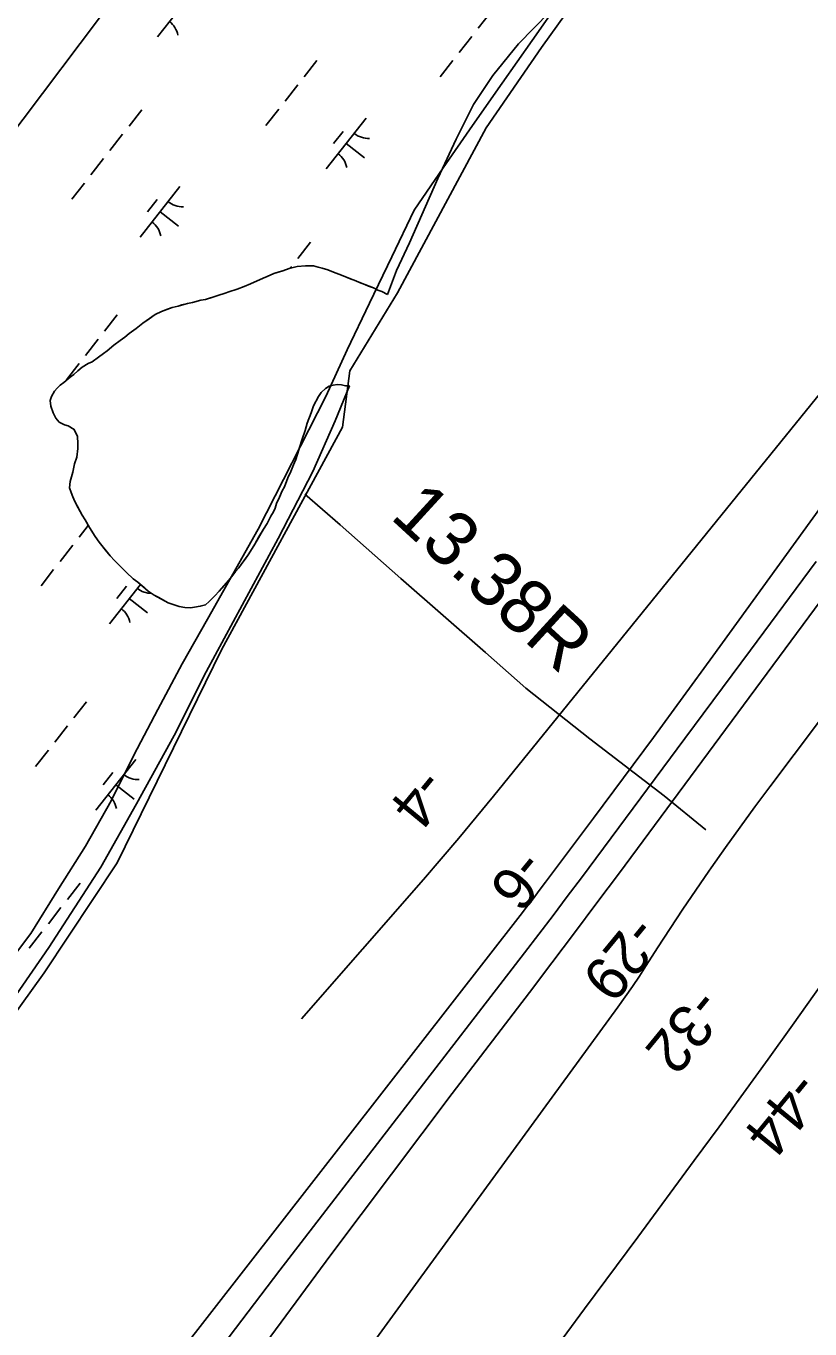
# Model space of a CAD drawing. Extents: x 3896831 to 3918110, y 171006 to 193349.
# Drawn here: x 3908456 to 3909064, y 182533 to 183545 of the extents above; entities that cross this region are included whole.
import ezdxf

# ---------------------------------------------------------------- set-up
doc = ezdxf.new("R2010")
doc.units = 0
for name, color, linetype in [('V-LEVE-TOET', 7, 'Continuous'), ('V-RIVR-EDGE', 7, 'Continuous'), ('V-RIVR-RANG', 7, 'Continuous'), ('V-RRAP-FSHR', 7, 'Continuous'), ('V-STRM-FMON', 7, 'Continuous'), ('V-TOPO-DPTH', 7, 'Continuous'), ('V-TOPO-MINR', 7, 'Continuous'), ('V-TOPO-SHOR', 7, 'Continuous'), ('V-UTIL-LINE', 7, 'Continuous'), ('V-WETL-SWMP', 7, 'Continuous')]:
    doc.layers.add(name, color=color, linetype=linetype)

msp = doc.modelspace()

# ---------------------------------------------------------------- linework, layer by layer
at = {"layer": 'V-LEVE-TOET'}
msp.add_lwpolyline([(3908983.2, 182920.7), (3908950.9, 182947.2), (3908893.3, 182991.3), (3908843.5, 183030.7), (3908812.3, 183058.4), (3908746.6, 183115.8), (3908699.5, 183157.6), (3908672.2, 183181.3)], dxfattribs=at)
at = {"layer": 'V-RIVR-EDGE'}
msp.add_lwpolyline([(3908938.3, 183643.2), (3908855.6, 183528), (3908812.8, 183465.7), (3908744, 183337.5), (3908706.9, 183277.1), (3908701.3, 183233.4), (3908607.5, 183060.6), (3908526.6, 182895.2), (3908469.9, 182809.7), (3908343.6, 182634.1), (3908310.1, 182599.7), (3908286.9, 182575.5), (3908257.1, 182538.4), (3908237.6, 182494.7), (3908204.2, 182458.4), (3908146.6, 182377.6), (3908019.3, 182222.4), (3907957, 182142.5), (3907934.7, 182118.4), (3907892, 182064.5), (3907843.6, 182017.1), (3907794.4, 181978)], dxfattribs=at)
at = {"layer": 'V-RRAP-FSHR'}
msp.add_lwpolyline([(3908870.9, 183565.8), (3908848.5, 183533.3), (3908825.1, 183500.2), (3908802.2, 183467.4), (3908779.3, 183434.6), (3908756.8, 183401.6), (3908739.5, 183365.6), (3908722.2, 183329.5), (3908704.9, 183293.4), (3908688.4, 183257), (3908635.8, 183154), (3908616.2, 183119.1), (3908596.5, 183084.3), (3908576.9, 183049.5), (3908558, 183014.2), (3908539.5, 182978.7), (3908521.9, 182943.2), (3908501.9, 182908.1), (3908480.9, 182874.9), (3908459.4, 182840.4), (3908435.9, 182808.9)], dxfattribs=at)
at = {"layer": 'V-TOPO-DPTH'}
for points in [[(3908466.3, 182375.2), (3908839.2, 182854.4), (3908844.1, 182860.8), (3908849.1, 182867.2), (3908854, 182873.7), (3908858.9, 182880.2), (3908895.9, 182929.7), (3908919.2, 182961.1), (3908942.5, 182992.5), (3908965.5, 183024), (3908988.5, 183055.6), (3909269, 183442.6)], [(3909374.9, 183409), (3909032.9, 182954.2), (3909021.3, 182938.6), (3909009.8, 182922.9), (3908998.5, 182907.1), (3908987.3, 182891.2), (3908985.5, 182888.7), (3908975.4, 182873.9), (3908965.4, 182859.1), (3908955.5, 182844.2), (3908945.8, 182829.2), (3908937, 182815.5), (3908931.6, 182807.3), (3908926.2, 182799.2), (3908920.6, 182791.2), (3908914.9, 182783.2), (3908760.1, 182570.7), (3908712, 182504.6)], [(3908712, 182504.6), (3908760.1, 182570.7), (3908914.9, 182783.2), (3908920.6, 182791.2), (3908926.2, 182799.2), (3908931.6, 182807.3), (3908937, 182815.5), (3908945.8, 182829.2), (3908955.5, 182844.2), (3908965.4, 182859.1), (3908975.4, 182873.9), (3908985.5, 182888.7), (3908987.3, 182891.2), (3908998.5, 182907.1), (3909009.8, 182922.9), (3909021.3, 182938.6), (3909032.9, 182954.2), (3909374.9, 183409)], [(3909122.5, 183166.5), (3908916.1, 182887.4), (3908898.7, 182864), (3908881.3, 182840.8), (3908863.8, 182817.6), (3908846.3, 182794.4), (3908786.5, 182716), (3908739.2, 182653.5), (3908692.3, 182590.8), (3908645.7, 182527.7), (3908599.5, 182464.5), (3908429.5, 182230.1), (3908422, 182219.8), (3908414.6, 182209.4), (3908407.3, 182199), (3908400, 182188.5), (3908378.2, 182157.1)], [(3908378.2, 182157.1), (3908400, 182188.5), (3908407.3, 182199), (3908414.6, 182209.4), (3908422, 182219.8), (3908429.5, 182230.1), (3908599.5, 182464.5), (3908645.7, 182527.7), (3908692.3, 182590.8), (3908739.2, 182653.5), (3908786.5, 182716), (3908846.3, 182794.4), (3908863.8, 182817.6), (3908881.3, 182840.8), (3908898.7, 182864), (3908916.1, 182887.4), (3909122.5, 183166.5)], [(3909253.5, 183055.4), (3909050.4, 182769.2), (3909031.5, 182742.8), (3909012.5, 182716.4), (3908993.4, 182690.2), (3908974.1, 182664), (3908930.3, 182604.7), (3908889.1, 182549), (3908847.9, 182493.2), (3908806.8, 182437.4), (3908765.7, 182381.6), (3908589.7, 182142.7), (3908578.7, 182127.6), (3908567.7, 182112.5), (3908556.7, 182097.4), (3908545.8, 182082.3), (3908506.8, 182027.9), (3908476.5, 181985.6), (3908446.1, 181943.2), (3908415.8, 181900.9), (3908385.4, 181858.5), (3908232.7, 181644.9)], [(3909253.5, 183055.4), (3909050.4, 182769.2), (3909031.5, 182742.8), (3909012.5, 182716.4), (3908993.4, 182690.2), (3908974.1, 182664), (3908930.3, 182604.7), (3908889.1, 182549), (3908847.9, 182493.2), (3908806.8, 182437.4), (3908765.7, 182381.6), (3908589.7, 182142.7), (3908578.7, 182127.6), (3908567.7, 182112.5), (3908556.7, 182097.4), (3908545.8, 182082.3), (3908506.8, 182027.9), (3908476.5, 181985.6), (3908446.1, 181943.2), (3908415.8, 181900.9), (3908385.4, 181858.5), (3908232.7, 181644.9)]]:
    msp.add_lwpolyline(points, dxfattribs=at)
at = {"layer": 'V-TOPO-MINR'}
for points in [[(3909295.6, 183556.8), (3909277.2, 183528.3), (3909258.1, 183500.2), (3909238.7, 183472.4), (3909218.8, 183444.9), (3909198.5, 183417.7), (3909177.8, 183390.8), (3909156.6, 183364.3), (3908818.5, 182946.9), (3908805.1, 182930.6), (3908791.6, 182914.4), (3908777.9, 182898.3), (3908764.1, 182882.3), (3908669.4, 182774)], [(3909269, 183442.6), (3908988.5, 183055.6), (3908965.5, 183024), (3908942.5, 182992.5), (3908919.2, 182961.1), (3908895.9, 182929.7), (3908858.9, 182880.2), (3908854, 182873.7), (3908849.1, 182867.2), (3908844.1, 182860.8), (3908839.2, 182854.4), (3908466.3, 182375.2)], [(3909374.9, 183409), (3909032.9, 182954.2), (3909021.3, 182938.6), (3909009.8, 182922.9), (3908998.5, 182907.1), (3908987.3, 182891.2), (3908985.5, 182888.7), (3908975.4, 182873.9), (3908965.4, 182859.1), (3908955.5, 182844.2), (3908945.8, 182829.2), (3908937, 182815.5), (3908931.6, 182807.3), (3908926.2, 182799.2), (3908920.6, 182791.2), (3908914.9, 182783.2), (3908760.1, 182570.7), (3908712, 182504.6)], [(3909122.5, 183166.5), (3908916.1, 182887.4), (3908898.7, 182864), (3908881.3, 182840.8), (3908863.8, 182817.6), (3908846.3, 182794.4), (3908786.5, 182716), (3908739.2, 182653.5), (3908692.3, 182590.8), (3908645.7, 182527.7), (3908599.5, 182464.5), (3908429.5, 182230.1), (3908422, 182219.8), (3908414.6, 182209.4), (3908407.3, 182199), (3908400, 182188.5), (3908378.2, 182157.1)], [(3909068.7, 183129), (3909017.8, 183060.3), (3908966.9, 182991.6), (3908886.6, 182883.6), (3908875.7, 182869), (3908864.7, 182854.4), (3908853.6, 182839.9), (3908842.5, 182825.4), (3908652.8, 182579), (3908608.4, 182520.9), (3908564.4, 182462.6), (3908520.8, 182403.8), (3908477.5, 182344.9), (3908418.3, 182263.6), (3908404.8, 182245.1), (3908391.3, 182226.7), (3908377.7, 182208.4), (3908364, 182190), (3908359.4, 182183.7), (3907444.9, 181069.3)], [(3909253.5, 183055.4), (3909050.4, 182769.2), (3909031.5, 182742.8), (3909012.5, 182716.4), (3908993.4, 182690.2), (3908974.1, 182664), (3908930.3, 182604.7), (3908889.1, 182549), (3908847.9, 182493.2), (3908806.8, 182437.4), (3908765.7, 182381.6), (3908589.7, 182142.7), (3908578.7, 182127.6), (3908567.7, 182112.5), (3908556.7, 182097.4), (3908545.8, 182082.3), (3908506.8, 182027.9), (3908476.5, 181985.6), (3908446.1, 181943.2), (3908415.8, 181900.9), (3908385.4, 181858.5), (3908232.7, 181644.9)]]:
    msp.add_lwpolyline(points, dxfattribs=at)
at = {"layer": 'V-TOPO-SHOR'}
for points in [[(3908518.7, 183292.6), (3908523.9, 183297), (3908528.8, 183300.5), (3908532.3, 183303.1), (3908535.7, 183306.1), (3908541.2, 183309.9), (3908546.4, 183314), (3908551.3, 183317.5), (3908555.9, 183320.7), (3908560.8, 183323.1), (3908564.8, 183324.6), (3908569.2, 183326.1), (3908573.8, 183327.3), (3908576.7, 183328.2), (3908581, 183329.4), (3908584.8, 183330), (3908591.4, 183331.8), (3908594.9, 183332.4), (3908600.7, 183334.2), (3908604.7, 183335.4), (3908610.2, 183337.2), (3908613.1, 183338.3), (3908619.5, 183340.4), (3908625, 183342.5), (3908629.9, 183344.6), (3908634.5, 183346.7), (3908639.7, 183349), (3908642.9, 183350.2), (3908648.1, 183352.6), (3908652.1, 183353.8), (3908655, 183354.7), (3908659.9, 183356.4), (3908666, 183357.9), (3908672.7, 183358.6), (3908678.8, 183358.4), (3908682.5, 183357.5), (3908685.4, 183356.7), (3908689.8, 183355.3), (3908694.2, 183353.6), (3908698.5, 183352.1), (3908703.2, 183350.2), (3908706.7, 183348.7), (3908711.6, 183346.8), (3908714.5, 183345.6), (3908718.6, 183343.9), (3908721.5, 183342.8), (3908725.3, 183341.4), (3908728.8, 183339.7), (3908731.7, 183338.5), (3908736.1, 183336.3)], [(3908706.8, 183265.5), (3908703.6, 183265.5), (3908700.4, 183266.1), (3908697.3, 183266.3), (3908694.1, 183266), (3908690.9, 183265.1), (3908688, 183263.3), (3908684.8, 183260.1), (3908682.6, 183257.2), (3908678.8, 183249.9), (3908676.9, 183244.4), (3908674, 183236.3), (3908672.3, 183230.7), (3908670.1, 183224.1), (3908667.8, 183216.8), (3908666.1, 183211.6), (3908665, 183208.1), (3908663.3, 183204), (3908661.3, 183198.8), (3908659, 183194.1), (3908656.2, 183187.1), (3908654.5, 183183.9), (3908652.5, 183179), (3908650.2, 183174), (3908649.1, 183170.5), (3908647.7, 183167.6), (3908645.7, 183164.1), (3908642.8, 183158.6), (3908640, 183154.2), (3908636.5, 183148.1), (3908633.4, 183142.6), (3908631.1, 183139.1), (3908628, 183134.1), (3908625.7, 183130.9), (3908622.8, 183126.8), (3908620.8, 183124.2), (3908618.2, 183121.3), (3908615.4, 183117.5), (3908612.8, 183114.3), (3908607.9, 183108.7), (3908605.6, 183106.1), (3908602.2, 183102.3), (3908597.9, 183097.9), (3908595, 183095.3), (3908590.9, 183094.3), (3908586.6, 183093.7), (3908583.4, 183093.1), (3908579.1, 183093.4), (3908574.7, 183094.2), (3908569.8, 183095.6), (3908566, 183097), (3908558.7, 183101), (3908555.2, 183103), (3908550.5, 183105.9), (3908547.3, 183108.8), (3908542.4, 183113.1), (3908538.8, 183115.6), (3908533.6, 183120.5), (3908528.3, 183126), (3908524.5, 183129.7), (3908521, 183133.4), (3908517.5, 183137.8), (3908512.5, 183144.1), (3908509.3, 183148.4), (3908504.9, 183155.3), (3908501.6, 183161.4), (3908499.3, 183165.1), (3908496.3, 183170.6), (3908493.7, 183175.5), (3908492.2, 183179.3), (3908490.7, 183182.5), (3908489.5, 183186.2), (3908490.1, 183191.2), (3908492, 183198.4), (3908493.4, 183204.8), (3908495.1, 183210), (3908495.9, 183216.7), (3908495.9, 183220.5), (3908495.6, 183226), (3908493.2, 183231.5), (3908488.5, 183234.3), (3908485.6, 183235.2), (3908481.5, 183237.2), (3908478.9, 183240.3), (3908476.8, 183244.4), (3908475.1, 183249.6), (3908474.4, 183253.9), (3908475.6, 183257.1), (3908477.8, 183261.2), (3908479.9, 183263.5), (3908482.2, 183265.9), (3908485, 183267.9), (3908489.9, 183272), (3908492.8, 183274.1), (3908496, 183277), (3908499.4, 183279.9), (3908504, 183282.6), (3908507.2, 183284.1), (3908512.1, 183287.6), (3908515.9, 183290.5), (3908518.7, 183292.6)]]:
    msp.add_lwpolyline(points, dxfattribs=at)
at = {"layer": 'V-UTIL-LINE'}
msp.add_lwpolyline([(3902278.5, 176090.1), (3904647.1, 178894.7), (3905719.5, 180143.9), (3906520.8, 181098.4), (3907322.1, 182041.1), (3907534.2, 182300.3), (3908041, 182924.9), (3909514, 184881.1), (3910138.5, 185694.2), (3909821.8, 185935.5), (3909829.3, 185945.1), (3909882.7, 185907)], dxfattribs=at)
at = {"layer": 'V-WETL-SWMP'}
for p, q in [((3908588.7, 183575.7), (3908557.8, 183536.3)), ((3908816.4, 183555.5), (3908806.6, 183542.9)), ((3908837.9, 183530.9), (3908861.8, 183555.3)), ((3908801.6, 183536.6), (3908791.8, 183524)), ((3908817.8, 183506.2), (3908837.9, 183530.9)), ((3908681.4, 183517.9), (3908671.5, 183505.3)), ((3908786.8, 183517.8), (3908777, 183505.2)), ((3908802.8, 183483.7), (3908817.8, 183506.2)), ((3908666.6, 183499), (3908656.7, 183486.4)), ((3908545.5, 183479.5), (3908535.7, 183466.9)), ((3908651.8, 183480.1), (3908641.9, 183467.5)), ((3908789.5, 183456.9), (3908802.8, 183483.7)), ((3908719.6, 183473.1), (3908688.7, 183433.7)), ((3908530.7, 183460.6), (3908520.8, 183448)), ((3908701.8, 183462.9), (3908694.4, 183453.4)), ((3908704.2, 183453.4), (3908718.3, 183442.3)), ((3908775.2, 183426.2), (3908789.5, 183456.9)), ((3908515.9, 183441.7), (3908506, 183429.1)), ((3908501.1, 183422.8), (3908491.2, 183410.3)), ((3908575.2, 183420.1), (3908544.4, 183380.8)), ((3908753.2, 183376.3), (3908775.2, 183426.2)), ((3908557.4, 183409.9), (3908550, 183400.5)), ((3908559.8, 183400.4), (3908574, 183389.3)), ((3908676.4, 183376.9), (3908666.6, 183364.3)), ((3908743.1, 183354.9), (3908753.2, 183376.3)), ((3908659.9, 183356.4), (3908666, 183357.9)), ((3908661.6, 183358), (3908660.5, 183356.6)), ((3908666, 183357.9), (3908672.7, 183358.6)), ((3908672.7, 183358.6), (3908678.8, 183358.4)), ((3908678.8, 183358.4), (3908682.5, 183357.5)), ((3908629.9, 183344.6), (3908639.7, 183349)), ((3908639.7, 183349), (3908642.9, 183350.2)), ((3908642.9, 183350.2), (3908648.1, 183352.6)), ((3908648.1, 183352.6), (3908655, 183354.7)), ((3908655, 183354.7), (3908659.9, 183356.4)), ((3908682.5, 183357.5), (3908685.4, 183356.7)), ((3908685.4, 183356.7), (3908689.8, 183355.3)), ((3908689.8, 183355.3), (3908694.2, 183353.6)), ((3908694.2, 183353.6), (3908698.5, 183352.1)), ((3908698.5, 183352.1), (3908703.2, 183350.2)), ((3908703.2, 183350.2), (3908718.6, 183343.9)), ((3908736.1, 183336.3), (3908743.1, 183354.9)), ((3908610.2, 183337.2), (3908613.1, 183338.3)), ((3908613.1, 183338.3), (3908619.5, 183340.4)), ((3908619.5, 183340.4), (3908625, 183342.5)), ((3908625, 183342.5), (3908629.9, 183344.6)), ((3908718.6, 183343.9), (3908725.3, 183341.4)), ((3908725.3, 183341.4), (3908728.8, 183339.7)), ((3908728.8, 183339.7), (3908731.7, 183338.5)), ((3908731.7, 183338.5), (3908736.1, 183336.3)), ((3908573.8, 183327.3), (3908581, 183329.4)), ((3908581, 183329.4), (3908584.8, 183330)), ((3908584.8, 183330), (3908591.4, 183331.8)), ((3908591.4, 183331.8), (3908594.9, 183332.4)), ((3908594.9, 183332.4), (3908604.7, 183335.4)), ((3908604.7, 183335.4), (3908610.2, 183337.2)), ((3908526.6, 183320.4), (3908516.7, 183307.8)), ((3908546.4, 183314), (3908555.9, 183320.7)), ((3908555.9, 183320.7), (3908560.8, 183323.1)), ((3908560.8, 183323.1), (3908569.2, 183326.1)), ((3908569.2, 183326.1), (3908573.8, 183327.3)), ((3908535.7, 183306.1), (3908541.2, 183309.9)), ((3908541.2, 183309.9), (3908546.4, 183314)), ((3908511.8, 183301.5), (3908501.9, 183288.9)), ((3908523.9, 183297), (3908528.8, 183300.5)), ((3908528.8, 183300.5), (3908532.3, 183303.1)), ((3908532.3, 183303.1), (3908535.7, 183306.1)), ((3908507.2, 183284.1), (3908512.1, 183287.6)), ((3908512.1, 183287.6), (3908515.9, 183290.5)), ((3908515.9, 183290.5), (3908518.7, 183292.6)), ((3908518.7, 183292.6), (3908523.9, 183297)), ((3908497, 183282.6), (3908487.1, 183270)), ((3908492.8, 183274.1), (3908496, 183277)), ((3908496, 183277), (3908499.4, 183279.9)), ((3908499.4, 183279.9), (3908504, 183282.6)), ((3908504, 183282.6), (3908507.2, 183284.1)), ((3908482.2, 183265.9), (3908485, 183267.9)), ((3908485, 183267.9), (3908489.9, 183272)), ((3908489.9, 183272), (3908492.8, 183274.1)), ((3908474.4, 183253.9), (3908475.6, 183257.1)), ((3908475.6, 183257.1), (3908477.8, 183261.2)), ((3908477.8, 183261.2), (3908479.9, 183263.5)), ((3908479.9, 183263.5), (3908482.2, 183265.9)), ((3908682.6, 183257.2), (3908678.8, 183249.9)), ((3908684.8, 183260.1), (3908682.6, 183257.2)), ((3908688, 183263.3), (3908684.8, 183260.1)), ((3908690.9, 183265.1), (3908688, 183263.3)), ((3908694.1, 183266), (3908690.9, 183265.1)), ((3908697.3, 183266.3), (3908694.1, 183266)), ((3908695.5, 183238.2), (3908706.8, 183265.5)), ((3908700.4, 183266.1), (3908697.3, 183266.3)), ((3908703.6, 183265.5), (3908700.4, 183266.1)), ((3908706.8, 183265.5), (3908703.6, 183265.5)), ((3908475.1, 183249.6), (3908474.4, 183253.9)), ((3908476.8, 183244.4), (3908475.1, 183249.6)), ((3908678.8, 183249.9), (3908676.9, 183244.4)), ((3908478.9, 183240.3), (3908476.8, 183244.4)), ((3908481.5, 183237.2), (3908478.9, 183240.3)), ((3908485.6, 183235.2), (3908481.5, 183237.2)), ((3908676.9, 183244.4), (3908674, 183236.3)), ((3908678.4, 183199), (3908695.5, 183238.2)), ((3908488.5, 183234.3), (3908485.6, 183235.2)), ((3908493.2, 183231.5), (3908488.5, 183234.3)), ((3908495.6, 183226), (3908493.2, 183231.5)), ((3908672.3, 183230.7), (3908670.1, 183224.1)), ((3908674, 183236.3), (3908672.3, 183230.7)), ((3908495.1, 183210), (3908495.9, 183216.7)), ((3908495.9, 183220.5), (3908495.6, 183226)), ((3908495.9, 183216.7), (3908495.9, 183220.5)), ((3908670.1, 183224.1), (3908665, 183208.1)), ((3908493.4, 183204.8), (3908495.1, 183210)), ((3908665, 183208.1), (3908663.3, 183204)), ((3908490.1, 183191.2), (3908492, 183198.4)), ((3908492, 183198.4), (3908493.4, 183204.8)), ((3908651.5, 183146.9), (3908678.4, 183199)), ((3908661.3, 183198.8), (3908659, 183194.1)), ((3908663.3, 183204), (3908661.3, 183198.8)), ((3908489.5, 183186.2), (3908490.1, 183191.2)), ((3908490.7, 183182.5), (3908489.5, 183186.2)), ((3908656.2, 183187.1), (3908654.5, 183183.9)), ((3908659, 183194.1), (3908656.2, 183187.1)), ((3908492.2, 183179.3), (3908490.7, 183182.5)), ((3908493.7, 183175.5), (3908492.2, 183179.3)), ((3908652.5, 183179), (3908650.2, 183174)), ((3908654.5, 183183.9), (3908652.5, 183179)), ((3908499.3, 183165.1), (3908493.7, 183175.5)), ((3908647.7, 183167.6), (3908645.7, 183164.1)), ((3908649.1, 183170.5), (3908647.7, 183167.6)), ((3908650.2, 183174), (3908649.1, 183170.5)), ((3908504, 183156.9), (3908497, 183147.9)), ((3908501.6, 183161.4), (3908499.3, 183165.1)), ((3908504.9, 183155.3), (3908501.6, 183161.4)), ((3908642.8, 183158.6), (3908640, 183154.2)), ((3908645.7, 183164.1), (3908642.8, 183158.6)), ((3908509.3, 183148.4), (3908504.9, 183155.3)), ((3908512.5, 183144.1), (3908509.3, 183148.4)), ((3908595.5, 183043.3), (3908651.5, 183146.9)), ((3908640, 183154.2), (3908633.4, 183142.6)), ((3908492, 183141.6), (3908482.2, 183129)), ((3908521, 183133.4), (3908512.5, 183144.1)), ((3908633.4, 183142.6), (3908628, 183134.1)), ((3908524.5, 183129.7), (3908521, 183133.4)), ((3908528.3, 183126), (3908524.5, 183129.7)), ((3908533.6, 183120.5), (3908528.3, 183126)), ((3908622.8, 183126.8), (3908620.8, 183124.2)), ((3908628, 183134.1), (3908622.8, 183126.8)), ((3908477.2, 183122.7), (3908467.4, 183110.1)), ((3908538.8, 183115.6), (3908533.6, 183120.5)), ((3908542.4, 183113.1), (3908538.8, 183115.6)), ((3908615.4, 183117.5), (3908612.8, 183114.3)), ((3908618.2, 183121.3), (3908615.4, 183117.5)), ((3908620.8, 183124.2), (3908618.2, 183121.3)), ((3908544.5, 183111.2), (3908520.5, 183080.6)), ((3908533.6, 183109.8), (3908526.2, 183100.3)), ((3908550.5, 183105.9), (3908542.4, 183113.1)), ((3908555.2, 183103), (3908550.5, 183105.9)), ((3908605.6, 183106.1), (3908602.2, 183102.3)), ((3908612.8, 183114.3), (3908605.6, 183106.1)), ((3908535.9, 183100.3), (3908550.1, 183089.2)), ((3908566, 183097), (3908555.2, 183103)), ((3908569.8, 183095.6), (3908566, 183097)), ((3908574.7, 183094.2), (3908569.8, 183095.6)), ((3908595, 183095.3), (3908590.9, 183094.3)), ((3908597.9, 183097.9), (3908595, 183095.3)), ((3908602.2, 183102.3), (3908597.9, 183097.9)), ((3908579.1, 183093.4), (3908574.7, 183094.2)), ((3908583.4, 183093.1), (3908579.1, 183093.4)), ((3908586.6, 183093.7), (3908583.4, 183093.1)), ((3908590.9, 183094.3), (3908586.6, 183093.7)), ((3908570.8, 182994.1), (3908595.5, 183043.3)), ((3908502.7, 183020.2), (3908492.8, 183007.6)), ((3908487.9, 183001.4), (3908478, 182988.8)), ((3908541.4, 182940.9), (3908570.8, 182994.1)), ((3908473.1, 182982.5), (3908463.2, 182969.9)), ((3908540.9, 182975.4), (3908510, 182936.1)), ((3908523.1, 182965.2), (3908515.7, 182955.8)), ((3908525.5, 182955.7), (3908539.6, 182944.6)), ((3908513.7, 182891.9), (3908541.4, 182940.9)), ((3908473.4, 182829.4), (3908513.7, 182891.9)), ((3908497.7, 182879.3), (3908487.9, 182866.7)), ((3908482.9, 182860.4), (3908473.1, 182847.8)), ((3908468.1, 182841.5), (3908458.3, 182828.9)), ((3908417.3, 182748.2), (3908473.4, 182829.4))]:
    msp.add_line(p, q, dxfattribs=at)
for centre, start, end in [((3908556.4, 183534.1), 11.1403, 52.6839), ((3908721.4, 183475), 231.1403, 272.6839), ((3908687.3, 183431.5), 11.1403, 52.6839), ((3908577, 183422), 231.1403, 272.6839), ((3908543, 183378.5), 11.1403, 52.6839), ((3908553.2, 183121.9), 231.1403, 269.9549), ((3908519.1, 183078.4), 11.1403, 52.6839), ((3908542.7, 182977.3), 231.1403, 272.6839), ((3908508.6, 182933.9), 11.1403, 52.6839)]:
    msp.add_arc(centre, 17.6, start, end, dxfattribs=at)

# ---------------------------------------------------------------- texts
at = {"layer": 'V-RIVR-RANG'}
for s, rotation, p in [('-4', 230.5183, (3908761.9, 182970.5)), ('-6', 230.5183, (3908839.3, 182907.2)), ('-29', 230.5183, (3908926.8, 182856.1)), ('-32', 230.6577, (3908975.7, 182799.9)), ('-44', 230.6577, (3909052.1, 182735.3))]:
    msp.add_text(s, height=33.5, rotation=rotation, dxfattribs=at).set_placement(p)
at = {"layer": 'V-STRM-FMON'}
msp.add_text('13.38R', height=42, rotation=317.5132, dxfattribs=at).set_placement((3908737.4, 183163.1))

doc.saveas('drawing.dxf')
